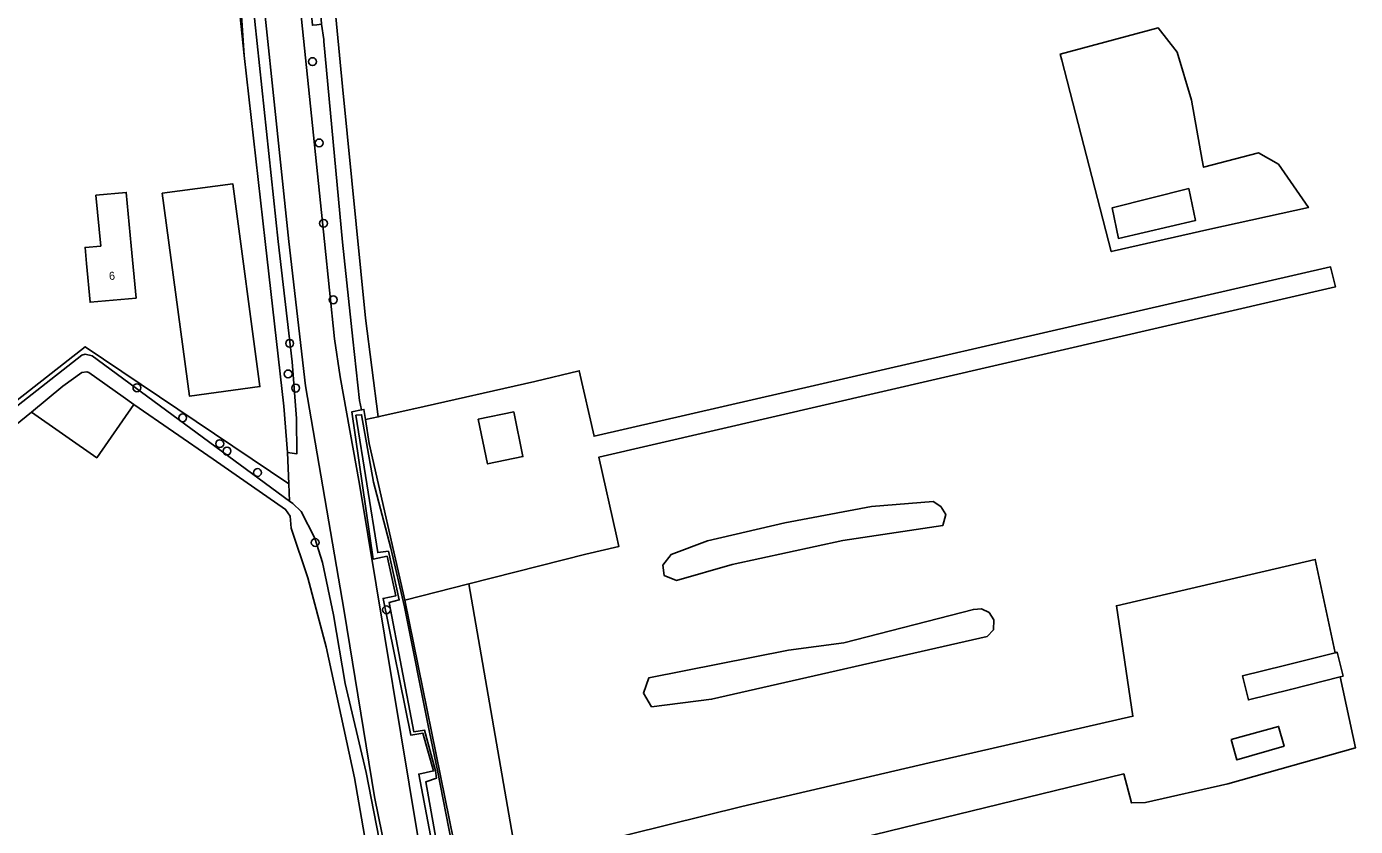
# Model space of a CAD drawing. Extents: x 163859 to 164644, y 379566 to 382155.
# Drawn here: x 164337.9 to 164503.9, y 381926.9 to 382026.8 of the extents above; entities that cross this region are included whole.
import ezdxf

# ---------------------------------------------------------------- set-up
doc = ezdxf.new("R2010")
doc.units = 0
for name, color, linetype in [('IMGEO_Boom', 7, 'Continuous'), ('IMGEO_Erf', 7, 'Continuous'), ('IMGEO_Grasland_agrarisch', 7, 'Continuous'), ('IMGEO_Grasland_overig', 7, 'Continuous'), ('IMGEO_Groenvoorziening', 7, 'Continuous'), ('IMGEO_Hek', 7, 'Continuous'), ('IMGEO_Loofbos', 7, 'Continuous'), ('IMGEO_Oever', 7, 'Continuous'), ('IMGEO_Pand', 7, 'Continuous'), ('IMGEO_Pand_nummerreeks', 7, 'Continuous'), ('IMGEO_Rijbaan_lokaal_halfverhard', 7, 'Continuous'), ('IMGEO_Waterloop', 7, 'Continuous')]:
    doc.layers.add(name, color=color, linetype=linetype)

msp = doc.modelspace()

# ---------------------------------------------------------------- linework, layer by layer
at = {"layer": 'IMGEO_Boom'}
for centre in [(164373.58, 382022.46), (164374.41, 382012.3), (164374.96, 382002.25), (164376.17, 381992.7), (164370.72, 381987.26), (164370.53, 381983.44), (164351.64, 381981.71), (164371.47, 381981.67), (164357.36, 381977.96), (164361.99, 381974.72), (164362.89, 381973.8), (164366.71, 381971.12), (164373.92, 381962.37), (164382.82, 381953.97)]:
    msp.add_circle(centre, 0.489, dxfattribs=at)
at = {"layer": 'IMGEO_Erf'}
for points in [[(164358.42, 382087.21), (164254.85, 381991.26), (164247.66, 381997.03), (164147.19, 381903.34), (164170.55, 381887.1), (164176.8, 381882.79), (164180.9, 381879.97), (164183.03, 381877.58), (164194.95, 381868.91), (164195.39, 381868.58), (164197.25, 381870.26), (164204.74, 381876.96), (164229.91, 381895.79), (164270.69, 381927.48), (164301.86, 381952.13), (164302.43, 381952.58), (164302.08, 381953.03), (164345.16, 381986.83), (164370.62, 381969.69), (164370.45, 381973.61), (164369.98, 381979.41), (164367.67, 382000), (164365.06, 382023.24)], [(164354.81, 382006.01), (164363.62, 382007.19), (164367.01, 381981.86), (164358.19, 381980.68)], [(164346.52, 382005.77), (164350.31, 382006.12), (164350.93, 381999.46), (164351.54, 381992.92), (164345.79, 381992.39), (164345.34, 381997.23), (164345.16, 381999.24), (164347.11, 381999.42)], [(164501.4, 381994.3), (164500.79, 381996.8), (164408.76, 381975.66), (164406.92, 381983.84), (164401.35, 381982.49), (164386.24, 381979.09), (164381.92, 381978.11), (164381.79, 381978.08), (164380.2, 381977.73), (164380.67, 381974.75), (164385.1, 381955.18), (164393.11, 381957.21), (164407.72, 381960.9), (164411.86, 381961.89), (164411.56, 381963.21), (164409.35, 381973.02)], [(164351.27, 381979.63), (164349.9, 381980.57), (164345.65, 381983.6), (164345.39, 381983.71), (164344.76, 381983.62), (164342.39, 381981.91), (164338.46, 381978.67), (164346.62, 381972.97)], [(164394.3, 381977.79), (164398.73, 381978.69), (164399.87, 381973.11), (164395.45, 381972.2)], [(164474.95, 381933.46), (164475.9, 381929.85), (164477.68, 381929.91), (164487.97, 381932.24), (164503.9, 381936.71), (164502.01, 381945.59), (164495.78, 381944.03), (164490.52, 381942.71), (164489.77, 381945.71), (164495.04, 381947.03), (164501.37, 381948.61), (164498.89, 381960.27), (164474.03, 381954.47), (164476.09, 381940.68), (164450.64, 381934.85), (164427.22, 381929.39), (164399.15, 381922.42), (164400.69, 381915.35)], [(164488.39, 381937.75), (164494.3, 381939.39), (164494.98, 381936.93), (164489.1, 381935.21)]]:
    msp.add_lwpolyline(points, close=True, dxfattribs=at)
at = {"layer": 'IMGEO_Grasland_agrarisch'}
for points in [[(164374.73, 382046.33), (164377.32, 382019.35), (164380.2, 381990.41), (164381.79, 381978.08), (164381.92, 381978.11), (164386.24, 381979.09), (164401.35, 381982.49), (164406.92, 381983.84), (164408.76, 381975.66), (164500.79, 381996.8), (164501.4, 381994.3), (164409.35, 381973.02), (164411.56, 381963.21), (164411.86, 381961.89), (164407.72, 381960.9), (164393.11, 381957.21), (164399.15, 381922.42), (164427.22, 381929.39), (164450.64, 381934.85), (164476.09, 381940.68), (164474.03, 381954.47), (164498.89, 381960.27), (164501.37, 381948.61), (164501.62, 381948.67), (164502.36, 381945.68), (164502.01, 381945.59), (164503.9, 381936.71), (164487.97, 381932.24), (164477.68, 381929.91), (164475.9, 381929.85), (164474.95, 381933.46), (164400.69, 381915.35)], [(164380.79, 381921.68), (164378.81, 381932.98), (164375.29, 381949.34), (164372.99, 381957.95), (164370.92, 381964.17), (164370.79, 381965.67), (164370.21, 381966.51), (164361.16, 381972.8), (164351.27, 381979.63), (164346.62, 381972.97), (164338.46, 381978.67), (164335.15, 381975.96), (164326.77, 381969.48), (164317.22, 381961.8), (164308.86, 381955.55), (164303.65, 381951.33), (164266.94, 381922.74)]]:
    msp.add_lwpolyline(points, dxfattribs=at)
for points in [[(164498.03, 382004.23), (164485.7, 382001.51), (164473.39, 381998.73), (164467.22, 382022.66), (164467.02, 382023.39), (164479.26, 382026.66), (164481.61, 382023.65), (164483.42, 382017.63), (164484.77, 382010.15), (164484.92, 382009.26), (164491.77, 382011.05), (164494.28, 382009.65)], [(164452.33, 381964.52), (164439.86, 381962.63), (164426.02, 381959.64), (164419.08, 381957.64), (164417.53, 381958.25), (164417.36, 381959.54), (164418.39, 381960.86), (164422.95, 381962.59), (164432.59, 381964.83), (164443.41, 381966.87), (164451.15, 381967.52), (164452.09, 381966.88), (164452.7, 381965.87)], [(164458.67, 381951.48), (164457.88, 381950.64), (164423.44, 381942.8), (164415.95, 381941.86), (164414.92, 381943.57), (164415.61, 381945.49), (164433.06, 381948.93), (164439.98, 381949.85), (164456.16, 381954.02), (164457.18, 381954.11), (164458.15, 381953.62), (164458.7, 381952.7)]]:
    msp.add_lwpolyline(points, close=True, dxfattribs=at)
at = {"layer": 'IMGEO_Grasland_overig'}
for points in [[(164380.2, 381977.73), (164381.79, 381978.08), (164380.2, 381990.41), (164377.32, 382019.35), (164374.73, 382046.33), (164371.92, 382069.69), (164369.59, 382090.41), (164367.77, 382090.28), (164368.05, 382088.47), (164369.5, 382079.3), (164372.99, 382051.45), (164374.69, 382027.13), (164374.98, 382025.23), (164375, 382024.99), (164377.32, 381999.91), (164378.62, 381987.8), (164379.45, 381980.13), (164379.72, 381978.95), (164380, 381979)], [(164483.42, 382017.63), (164481.61, 382023.65), (164479.26, 382026.66), (164467.02, 382023.39), (164467.22, 382022.66), (164473.39, 381998.73), (164485.7, 382001.51), (164498.03, 382004.23), (164494.28, 382009.65), (164491.77, 382011.05), (164484.92, 382009.26), (164484.77, 382010.15)], [(164483.1, 382006.59), (164483.93, 382002.61), (164474.29, 382000.37), (164473.5, 382004.19)], [(164370.71, 381967.54), (164370.62, 381969.69), (164345.16, 381986.83), (164302.08, 381953.03), (164302.43, 381952.58), (164344.76, 381985.77), (164345.16, 381985.92), (164346.03, 381985.72)], [(164417.36, 381959.54), (164417.53, 381958.25), (164419.08, 381957.64), (164426.02, 381959.64), (164439.86, 381962.63), (164452.33, 381964.52), (164452.7, 381965.87), (164452.09, 381966.88), (164451.15, 381967.52), (164443.41, 381966.87), (164432.59, 381964.83), (164422.95, 381962.59), (164418.39, 381960.86)], [(164385.1, 381955.18), (164391.22, 381925.04), (164392.24, 381918.62), (164392.84, 381914.85), (164394.3, 381906.15), (164395.74, 381897.51), (164395.98, 381896.47), (164398.12, 381897.01), (164404.87, 381898.71), (164400.69, 381915.35), (164399.15, 381922.42), (164393.11, 381957.21)], [(164415.61, 381945.49), (164414.92, 381943.57), (164415.95, 381941.86), (164423.44, 381942.8), (164457.88, 381950.64), (164458.67, 381951.48), (164458.7, 381952.7), (164458.15, 381953.62), (164457.18, 381954.11), (164456.16, 381954.02), (164439.98, 381949.85), (164433.06, 381948.93)]]:
    msp.add_lwpolyline(points, close=True, dxfattribs=at)
at = {"layer": 'IMGEO_Groenvoorziening'}
for points in [[(164377.32, 381999.91), (164375, 382024.99), (164374.98, 382025.23), (164374.69, 382027.13), (164374.12, 382027.07), (164373.56, 382027.01), (164371.07, 382052.25), (164369.31, 382067.96), (164367.5, 382080), (164366.21, 382089.98), (164363.36, 382106.67), (164361.94, 382106.41), (164362.19, 382105.09), (164364.66, 382091.74), (164366.23, 382081.36), (164368.33, 382065.24), (164375.07, 382000), (164376.33, 381987.84), (164377.03, 381983.08), (164379.47, 381969.66), (164387.74, 381919.59), (164388.1, 381917.44), (164394.68, 381881.88)], [(164390.52, 381880.76), (164384.14, 381916.84), (164383.71, 381918.93), (164381.31, 381930.61), (164377.52, 381953.78), (164372.7, 381981.96), (164370.62, 382000), (164365.91, 382044.84), (164361.43, 382082.09), (164360.43, 382089.08), (164359.08, 382087.82)], [(164359.08, 382087.82), (164359.75, 382083.3), (164360.54, 382083.2), (164363.01, 382063.74), (164364.97, 382044.42), (164366.37, 382027.45), (164369.27, 382000), (164371.04, 381984.97), (164371.58, 381977.88), (164371.64, 381973.47), (164370.45, 381973.61), (164370.62, 381969.69), (164370.71, 381967.54), (164371.12, 381967.24), (164372.16, 381966.25), (164373.87, 381962.9), (164374.84, 381959.88), (164376.2, 381953.33), (164377.66, 381944.75), (164380.3, 381933.65), (164382.52, 381922.1)], [(164389.46, 381919.87), (164386.85, 381933.44), (164388.7, 381933.84), (164387.38, 381938.54), (164385.86, 381938.31), (164382.4, 381955.4), (164384, 381955.72), (164382.9, 381960.67), (164381.18, 381960.3), (164378.51, 381978.71), (164379.72, 381978.95), (164379.45, 381980.13), (164378.62, 381987.8), (164377.32, 381999.91)]]:
    msp.add_lwpolyline(points, dxfattribs=at)
at = {"layer": 'IMGEO_Hek'}
for points in [[(164358.42, 382087.21), (164365.06, 382023.24)], [(164302.08, 381953.03), (164345.16, 381986.83), (164370.62, 381969.69)], [(164385.1, 381955.18), (164380.67, 381974.75)], [(164385.1, 381955.18), (164391.22, 381925.04), (164392.24, 381918.62)]]:
    msp.add_lwpolyline(points, dxfattribs=at)
at = {"layer": 'IMGEO_Loofbos'}
msp.add_lwpolyline([(164359.08, 382087.82), (164358.42, 382087.21), (164365.06, 382023.24), (164363.18, 382051.25), (164361.4, 382069.61), (164359.75, 382083.3)], close=True, dxfattribs=at)
at = {"layer": 'IMGEO_Oever'}
for points in [[(164391.22, 381925.04), (164385.1, 381955.18), (164380.67, 381974.75), (164380.2, 381977.73), (164380, 381979), (164379.72, 381978.95), (164378.51, 381978.71), (164381.18, 381960.3), (164382.9, 381960.67), (164384, 381955.72), (164382.4, 381955.4), (164385.86, 381938.31), (164387.38, 381938.54), (164388.7, 381933.84), (164386.85, 381933.44), (164389.46, 381919.87)], [(164393.21, 381901.8), (164387.75, 381932.48), (164389.09, 381932.95), (164388.94, 381933.87), (164387.58, 381938.93), (164386.23, 381938.73), (164383.15, 381954.87), (164384.42, 381955.21), (164383.06, 381961.28), (164381.74, 381961.11), (164379.01, 381978.27), (164379.71, 381978.33), (164381.21, 381969.92), (164383.38, 381961.66), (164385.06, 381954.36), (164388.16, 381938.91), (164389.26, 381933.7), (164390.96, 381924.95)]]:
    msp.add_lwpolyline(points, dxfattribs=at)
at = {"layer": 'IMGEO_Pand'}
for points in [[(164354.81, 382006.01), (164358.19, 381980.68), (164367.01, 381981.86), (164363.62, 382007.19)], [(164350.93, 381999.46), (164350.31, 382006.12), (164346.52, 382005.77), (164347.11, 381999.42), (164345.16, 381999.24), (164345.34, 381997.23), (164345.79, 381992.39), (164351.54, 381992.92)], [(164483.1, 382006.59), (164473.5, 382004.19), (164474.29, 382000.37), (164483.93, 382002.61)], [(164394.3, 381977.79), (164395.45, 381972.2), (164399.87, 381973.11), (164398.73, 381978.69)], [(164501.37, 381948.61), (164495.04, 381947.03), (164489.77, 381945.71), (164490.52, 381942.71), (164495.78, 381944.03), (164502.01, 381945.59), (164502.36, 381945.68), (164501.62, 381948.67)], [(164488.39, 381937.75), (164489.1, 381935.21), (164494.98, 381936.93), (164494.3, 381939.39)]]:
    msp.add_lwpolyline(points, close=True, dxfattribs=at)
at = {"layer": 'IMGEO_Rijbaan_lokaal_halfverhard'}
for points in [[(164394.68, 381881.88), (164388.1, 381917.44), (164387.74, 381919.59), (164379.47, 381969.66), (164377.03, 381983.08), (164376.33, 381987.84), (164375.07, 382000), (164368.33, 382065.24), (164366.23, 382081.36), (164364.66, 382091.74), (164362.19, 382105.09), (164359.32, 382104.56), (164361.73, 382090.28), (164360.43, 382089.08)], [(164360.43, 382089.08), (164361.43, 382082.09), (164365.91, 382044.84), (164370.62, 382000), (164372.7, 381981.96), (164377.52, 381953.78), (164381.31, 381930.61), (164383.71, 381918.93), (164384.14, 381916.84), (164390.52, 381880.76)]]:
    msp.add_lwpolyline(points, dxfattribs=at)
at = {"layer": 'IMGEO_Waterloop'}
msp.add_lwpolyline([(164370.45, 381973.61), (164371.64, 381973.47), (164371.58, 381977.88), (164371.04, 381984.97), (164369.27, 382000), (164366.37, 382027.45), (164364.97, 382044.42), (164363.01, 382063.74), (164360.54, 382083.2), (164359.75, 382083.3), (164361.4, 382069.61), (164363.18, 382051.25), (164365.06, 382023.24), (164367.67, 382000), (164369.98, 381979.41)], close=True, dxfattribs=at)
for points in [[(164382.52, 381922.1), (164380.3, 381933.65), (164377.66, 381944.75), (164376.2, 381953.33), (164374.84, 381959.88), (164373.87, 381962.9), (164372.16, 381966.25), (164371.12, 381967.24), (164370.71, 381967.54), (164346.03, 381985.72), (164345.16, 381985.92), (164344.76, 381985.77), (164302.43, 381952.58), (164301.86, 381952.13), (164270.69, 381927.48), (164229.91, 381895.79)], [(164266.94, 381922.74), (164303.65, 381951.33), (164308.86, 381955.55), (164317.22, 381961.8), (164326.77, 381969.48), (164335.15, 381975.96), (164338.46, 381978.67), (164342.39, 381981.91), (164344.76, 381983.62), (164345.39, 381983.71), (164345.65, 381983.6), (164349.9, 381980.57), (164351.27, 381979.63), (164361.16, 381972.8), (164370.21, 381966.51), (164370.79, 381965.67), (164370.92, 381964.17), (164372.99, 381957.95), (164375.29, 381949.34), (164378.81, 381932.98), (164380.79, 381921.68)], [(164390.96, 381924.95), (164389.26, 381933.7), (164388.16, 381938.91), (164385.06, 381954.36), (164383.38, 381961.66), (164381.21, 381969.92), (164379.71, 381978.33), (164379.01, 381978.27), (164381.74, 381961.11), (164383.06, 381961.28), (164384.42, 381955.21), (164383.15, 381954.87), (164386.23, 381938.73), (164387.58, 381938.93), (164388.94, 381933.87), (164389.09, 381932.95), (164387.75, 381932.48), (164393.21, 381901.8)]]:
    msp.add_lwpolyline(points, dxfattribs=at)

# ---------------------------------------------------------------- texts
at = {"layer": 'IMGEO_Pand_nummerreeks'}
msp.add_text('6', height=1, rotation=4.7097, dxfattribs=at).set_placement((164348.19, 381995.17))

doc.saveas('drawing.dxf')
